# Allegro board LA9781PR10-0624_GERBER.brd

Outline 305.85 x 179.2 mm; copper layers: TOP, GND1, IN1, VCC, IN2, IN3, GND2, IN4, GND3, BOTTOM. Coordinates in mm from the lower left corner of the outline.

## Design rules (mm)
net group BUS_CSS: nets CSSN_1 CSSP_1
net group BUS_FDI-CTL: nets FDI_CSYNC FDI_INT
net group BUS_SMB: nets GPU_SMBCLK_R GPU_SMBDAT_R
net group BUS_SVID: nets PECI_EC PECI_EC_R
net group CLK_CPU_DMI: nets CLK_CPU_DMI CPU_DMI
net group CLK_CPU_DMI#: nets CLK_CPU_DMI# CPU_DMI#
net group CLK_CPU_DPLL: nets CLK_CPU_DPLL CPU_DPLL
net group CLK_CPU_DPLL#: nets CLK_CPU_DPLL# CPU_DPLL#
net group CLK_CPU_SSC_DPLL: nets CLK_CPU_SSC_DPLL CPU_SSC_DPLL
net group CLK_CPU_SSC_DPLL#: nets CLK_CPU_SSC_DPLL# CPU_SSC_DPLL#
net group CLK_PCIE_CARD: nets CLK_PCIE_CARD PCIE_CARD
net group CLK_PCIE_CARD#: nets CLK_PCIE_CARD# PCIE_CARD#
net group CLK_PCIE_EXP: nets CLK_PCIE_EXP PCIE_EXP
net group CLK_PCIE_EXP#: nets CLK_PCIE_EXP# PCIE_EXP#
net group CLK_PCIE_LAN: nets CLK_PCIE_LAN PCIE_LAN
net group CLK_PCIE_LAN#: nets CLK_PCIE_LAN# PCIE_LAN#
net group CLK_PCIE_MINI1: nets CLK_PCIE_MINI1 PCIE_MINI1
net group CLK_PCIE_MINI1#: nets CLK_PCIE_MINI1# PCIE_MINI1#
net group CLK_PCIE_MINI3: nets CLK_PCIE_MINI3 PCIE_MINI3
net group CLK_PCIE_MINI3#: nets CLK_PCIE_MINI3# PCIE_MINI3#
net group CLK_PCIE_NVR: nets CLK_PCIE_NVR PCIE_NVR
net group CLK_PCIE_NVR#: nets CLK_PCIE_NVR# PCIE_NVR#
net group DDR_XDP_WAN_SMBCLK: nets DDR_XDP_WAN_SMBCLK DDR_XDP_WAN_SMBCLK_R2
net group DDR_XDP_WAN_SMBDAT: nets DDR_XDP_WAN_SMBDAT DDR_XDP_WAN_SMBDAT_R2
net group DIFFPAIR0: nets MXM_CURI2C_CLK MXM_CURI2C_DATA
net group DP_CARD_SMBCD: nets CARD_SMBCLK CARD_SMBDAT
net group DP_CHARGER_SMBCD: nets CHARGER_SMBCLK CHARGER_SMBDAT
net group DP_CLK_BUF_BCLK: nets CLK_BUF_BCLK CLK_BUF_BCLK#
net group DP_CLK_BUF_DMI: nets CLK_BUF_DMI CLK_BUF_DMI#
net group DP_CLK_PCIE_MINI2: nets CLK_PCIE_MINI2 CLK_PCIE_MINI2#
net group DP_DOCK_SMBCD: nets DOCK_SMB_CLK DOCK_SMB_DAT
net group DP_DPC_DOCK_SW_AUX: nets DPC_DOCK_SW_AUX DPC_DOCK_SW_AUX#
net group DP_DPD_DOCK_AUX: nets DPD_DOCK_AUX DPD_DOCK_AUX#
net group DP_EDP_CPU_AUX-R: nets EDP_CPU_AUX#_R EDP_CPU_AUX_R
net group DP_GPU_SMBCD: nets GPU_SMBCLK GPU_SMBDAT
net group DP_LAN_SMBCD: nets LAN_SMBCLK LAN_SMBDATA
net group DP_LAN_TX0: nets LAN_TX0+R LAN_TX0-R
net group DP_LAN_TX1+R: nets LAN_TX1+R LAN_TX1-R
net group DP_LAN_TX2: nets LAN_TX2+ LAN_TX2-
net group DP_LAN_TX2+R: nets LAN_TX2+R LAN_TX2-R
net group DP_LAN_TX3: nets LAN_TX3+ LAN_TX3-
net group DP_LCD_SMBCD: nets LCD_SMBCLK LCD_SMBDAT
net group DP_LDDC-SW: nets LDDC_CLK_SW LDDC_DATA_SW
net group DP_LVDS_B0: nets LVDS_B0+ LVDS_B0-
net group DP_MEM_SMBCD: nets MEM_SMBCLK MEM_SMBDATA
net group DP_MUX_AUX: nets MUX_AUX MUX_AUX#
net group DP_PBAT_SMBCD: nets PBAT_SMBCLK PBAT_SMBDAT
net group DP_SML1_SMBCD: nets SML1_SMBCLK SML1_SMBDATA
net group DP_SW_LVDS_A0: nets SW_LVDS_A0+ SW_LVDS_A0-
net group DP_SW_LVDS_A1: nets SW_LVDS_A1+ SW_LVDS_A1-
net group DP_SW_LVDS_A2: nets SW_LVDS_A2+ SW_LVDS_A2-
net group DP_SW_LVDS_ACLK: nets SW_LVDS_ACLK+ SW_LVDS_ACLK-
net group DP_SW_LVDS_B0: nets SW_LVDS_B0+ SW_LVDS_B0-
net group DP_SW_LVDS_B1: nets SW_LVDS_B1+ SW_LVDS_B1-
net group DP_SW_LVDS_B2: nets SW_LVDS_B2+ SW_LVDS_B2-
net group DP_SW_LVDS_BCLK: nets SW_LVDS_BCLK+ SW_LVDS_BCLK-
net group DP_USB3R5: nets USB3RN5 USB3RP5
net group DP_USB3R6: nets USB3RN6 USB3RP6
net group DP_USB3T3: nets USB3TN3 USB3TP3
net group DP_USB3T5: nets USB3TN5 USB3TP5
net group DP_USB3T6: nets USB3TN6 USB3TP6
net group DP_USBP1: nets USBP1+ USBP1-
net group DP_USBP2: nets USBP2+ USBP2-
net group DP_USBP5: nets USBP5+ USBP5-
net group DP_USBP9: nets USBP9+ USBP9-
net group DP_USBP10: nets USBP10+ USBP10-
net group DP_USBP11: nets USBP11+ USBP11-
net group DP_USH_SMBCD: nets USH_SMBCLK USH_SMBDAT
net group DP_Z430_SMBCD: nets Z4304 Z4305
net group DPD_CPU_LANE_N0: nets DPD_CPU_LANE_N0 DPD_CPU_LANE_N0_C
net group DPD_CPU_LANE_N1: nets DPD_CPU_LANE_N1 DPD_CPU_LANE_N1_C
net group DPD_CPU_LANE_N2: nets DPD_CPU_LANE_N2 DPD_CPU_LANE_N2_C
net group DPD_CPU_LANE_N3: nets DPD_CPU_LANE_N3 DPD_CPU_LANE_N3_C
net group DPD_CPU_LANE_P0: nets DPD_CPU_LANE_P0 DPD_CPU_LANE_P0_C
net group DPD_CPU_LANE_P1: nets DPD_CPU_LANE_P1 DPD_CPU_LANE_P1_C
net group DPD_CPU_LANE_P2: nets DPD_CPU_LANE_P2 DPD_CPU_LANE_P2_C
net group DPD_CPU_LANE_P3: nets DPD_CPU_LANE_P3 DPD_CPU_LANE_P3_C
net group MB_DP_RP_C_N0: nets MB_DP_RP_C_N0 MB_DP_RP_N0
net group MB_DP_RP_C_N1: nets MB_DP_RP_C_N1 MB_DP_RP_N1
net group MB_DP_RP_C_N2: nets MB_DP_RP_C_N2 MB_DP_RP_N2
net group MB_DP_RP_C_N3: nets MB_DP_RP_C_N3 MB_DP_RP_N3
net group MB_DP_RP_C_P0: nets MB_DP_RP_C_P0 MB_DP_RP_P0
net group MB_DP_RP_C_P1: nets MB_DP_RP_C_P1 MB_DP_RP_P1
net group MB_DP_RP_C_P2: nets MB_DP_RP_C_P2 MB_DP_RP_P2
net group MB_DP_RP_C_P3: nets MB_DP_RP_C_P3 MB_DP_RP_P3
net group MSATA_PRX_DTX_N4: nets MSATA_PRX_DTX_N4 MSATA_PRX_DTX_N4_C
net group MSATA_PRX_DTX_P4: nets MSATA_PRX_DTX_P4 MSATA_PRX_DTX_P4_C
net group MSATA_PTX_DRX_N4: nets MSATA_PTX_DRX_N4 MSATA_PTX_DRX_N4_C
net group MSATA_PTX_DRX_P4: nets MSATA_PTX_DRX_P4 MSATA_PTX_DRX_P4_C
net group MUX_D0: nets MUX_D0 MUX_D0_C
net group MUX_D0#: nets MUX_D0# MUX_D0#_C
net group MUX_D1: nets MUX_D1 MUX_D1_C
net group MUX_D1#: nets MUX_D1# MUX_D1#_C
net group MUX_D2: nets MUX_D2 MUX_D2_C
net group MUX_D2#: nets MUX_D2# MUX_D2#_C
net group MUX_D3: nets MUX_D3 MUX_D3_C
net group MUX_D3#: nets MUX_D3# MUX_D3#_C
net group MXM_DPC_AUX: nets MXM_DPC_AUX MXM_DPC_AUX_C
net group MXM_DPC_AUX#: nets MXM_DPC_AUX# MXM_DPC_AUX#_C
net group MXM_DPC_N0: nets MXM_DPC_N0 MXM_DPC_N0_C
net group MXM_DPC_N1: nets MXM_DPC_N1 MXM_DPC_N1_C
net group MXM_DPC_N2: nets MXM_DPC_N2 MXM_DPC_N2_C
net group MXM_DPC_N3: nets MXM_DPC_N3 MXM_DPC_N3_C
net group MXM_DPC_P0: nets MXM_DPC_P0 MXM_DPC_P0_C
net group MXM_DPC_P1: nets MXM_DPC_P1 MXM_DPC_P1_C
net group MXM_DPC_P2: nets MXM_DPC_P2 MXM_DPC_P2_C
net group MXM_DPC_P3: nets MXM_DPC_P3 MXM_DPC_P3_C
net group MXM_EDP_AUX+: nets MXM_EDP_AUX+ MXM_EDP_AUX+_C
net group MXM_EDP_AUX-: nets MXM_EDP_AUX- MXM_EDP_AUX-_C
net group MXM_EDP_TX0+: nets MXM_EDP_TX0+ MXM_EDP_TX0+_C
net group MXM_EDP_TX0-: nets MXM_EDP_TX0- MXM_EDP_TX0-_C
net group MXM_EDP_TX1+: nets MXM_EDP_TX1+ MXM_EDP_TX1+_C
net group MXM_EDP_TX1-: nets MXM_EDP_TX1- MXM_EDP_TX1-_C
net group MXM_EDP_TX2+: nets MXM_EDP_TX2+ MXM_EDP_TX2+_C
net group MXM_EDP_TX2-: nets MXM_EDP_TX2- MXM_EDP_TX2-_C
net group MXM_EDP_TX3+: nets MXM_EDP_TX3+ MXM_EDP_TX3+_C
net group MXM_EDP_TX3-: nets MXM_EDP_TX3- MXM_EDP_TX3-_C
net group MXM_MB_DP_N0: nets MXM_MB_DP_N0 MXM_MB_DP_N0_C
net group MXM_MB_DP_N1: nets MXM_MB_DP_N1 MXM_MB_DP_N1_C
net group MXM_MB_DP_N2: nets MXM_MB_DP_N2 MXM_MB_DP_N2_C
net group MXM_MB_DP_N3: nets MXM_MB_DP_N3 MXM_MB_DP_N3_C
net group MXM_MB_DP_P0: nets MXM_MB_DP_P0 MXM_MB_DP_P0_C
net group MXM_MB_DP_P1: nets MXM_MB_DP_P1 MXM_MB_DP_P1_C
net group MXM_MB_DP_P2: nets MXM_MB_DP_P2 MXM_MB_DP_P2_C
net group MXM_MB_DP_P3: nets MXM_MB_DP_P3 MXM_MB_DP_P3_C
net group NB_LAN_TX0+: nets NB_LAN_TX0+ NB_LAN_TX0+_R
net group NB_LAN_TX0-: nets NB_LAN_TX0- NB_LAN_TX0-_R
net group NB_LAN_TX1+: nets NB_LAN_TX1+ NB_LAN_TX1+_R
net group NB_LAN_TX1-: nets NB_LAN_TX1- NB_LAN_TX1-_R
net group PCH_DDPD_AUX: nets PCH_DDPD_AUX PCH_DDPD_AUX_C
net group PCH_DDPD_AUX#: nets PCH_DDPD_AUX# PCH_DDPD_AUX#_C
net group PCIE_PRX_GLANTX_N2: nets PCIE_PRX_GLANTX_N2 PCIE_PRX_GLANTX_N2_C
net group PCIE_PRX_GLANTX_P2: nets PCIE_PRX_GLANTX_P2 PCIE_PRX_GLANTX_P2_C
net group PCIE_PTX_GLANRX_N2: nets PCIE_PTX_GLANRX_N2 PCIE_PTX_GLANRX_N2_C
net group PCIE_PTX_GLANRX_P2: nets PCIE_PTX_GLANRX_P2 PCIE_PTX_GLANRX_P2_C
net group PCIE_PTX_WANRX_N5: nets PCIE_PTX_WANRX_N5 PCIE_PTX_WANRX_N5_C
net group PCIE_PTX_WANRX_P5: nets PCIE_PTX_WANRX_P5 PCIE_PTX_WANRX_P5_C
net group PCIE_PTX_WLANRX_N3: nets PCIE_PTX_WLANRX_N3 PCIE_PTX_WLANRX_N3_C
net group PCIE_PTX_WLANRX_P3: nets PCIE_PTX_WLANRX_P3 PCIE_PTX_WLANRX_P3_C
net group PCIE_PTX_WPANRX_N6: nets PCIE_PTX_WPANRX_N6 PCIE_PTX_WPANRX_N6_C
net group PCIE_PTX_WPANRX_P6: nets PCIE_PTX_WPANRX_P6 PCIE_PTX_WPANRX_P6_C
net group PEG_CRX_GTX_C_N0: nets PEG_CRX_GTX_C_N0 PEG_CRX_GTX_N0
net group PEG_CRX_GTX_C_N1: nets PEG_CRX_GTX_C_N1 PEG_CRX_GTX_N1
net group PEG_CRX_GTX_C_N2: nets PEG_CRX_GTX_C_N2 PEG_CRX_GTX_N2
net group PEG_CRX_GTX_C_N3: nets PEG_CRX_GTX_C_N3 PEG_CRX_GTX_N3
net group PEG_CRX_GTX_C_N4: nets PEG_CRX_GTX_C_N4 PEG_CRX_GTX_N4
net group PEG_CRX_GTX_C_N5: nets PEG_CRX_GTX_C_N5 PEG_CRX_GTX_N5
net group PEG_CRX_GTX_C_N6: nets PEG_CRX_GTX_C_N6 PEG_CRX_GTX_N6
net group PEG_CRX_GTX_C_N7: nets PEG_CRX_GTX_C_N7 PEG_CRX_GTX_N7
net group PEG_CRX_GTX_C_N8: nets PEG_CRX_GTX_C_N8 PEG_CRX_GTX_N8
net group PEG_CRX_GTX_C_N9: nets PEG_CRX_GTX_C_N9 PEG_CRX_GTX_N9
net group PEG_CRX_GTX_C_N10: nets PEG_CRX_GTX_C_N10 PEG_CRX_GTX_N10
net group PEG_CRX_GTX_C_N11: nets PEG_CRX_GTX_C_N11 PEG_CRX_GTX_N11
net group PEG_CRX_GTX_C_N12: nets PEG_CRX_GTX_C_N12 PEG_CRX_GTX_N12
net group PEG_CRX_GTX_C_N13: nets PEG_CRX_GTX_C_N13 PEG_CRX_GTX_N13
net group PEG_CRX_GTX_C_N14: nets PEG_CRX_GTX_C_N14 PEG_CRX_GTX_N14
net group PEG_CRX_GTX_C_N15: nets PEG_CRX_GTX_C_N15 PEG_CRX_GTX_N15
net group PEG_CRX_GTX_C_P0: nets PEG_CRX_GTX_C_P0 PEG_CRX_GTX_P0
net group PEG_CRX_GTX_C_P1: nets PEG_CRX_GTX_C_P1 PEG_CRX_GTX_P1
net group PEG_CRX_GTX_C_P2: nets PEG_CRX_GTX_C_P2 PEG_CRX_GTX_P2
net group PEG_CRX_GTX_C_P3: nets PEG_CRX_GTX_C_P3 PEG_CRX_GTX_P3
net group PEG_CRX_GTX_C_P4: nets PEG_CRX_GTX_C_P4 PEG_CRX_GTX_P4
net group PEG_CRX_GTX_C_P5: nets PEG_CRX_GTX_C_P5 PEG_CRX_GTX_P5
net group PEG_CRX_GTX_C_P6: nets PEG_CRX_GTX_C_P6 PEG_CRX_GTX_P6
net group PEG_CRX_GTX_C_P7: nets PEG_CRX_GTX_C_P7 PEG_CRX_GTX_P7
net group PEG_CRX_GTX_C_P8: nets PEG_CRX_GTX_C_P8 PEG_CRX_GTX_P8
net group PEG_CRX_GTX_C_P9: nets PEG_CRX_GTX_C_P9 PEG_CRX_GTX_P9
net group PEG_CRX_GTX_C_P10: nets PEG_CRX_GTX_C_P10 PEG_CRX_GTX_P10
net group PEG_CRX_GTX_C_P11: nets PEG_CRX_GTX_C_P11 PEG_CRX_GTX_P11
net group PEG_CRX_GTX_C_P12: nets PEG_CRX_GTX_C_P12 PEG_CRX_GTX_P12
net group PEG_CRX_GTX_C_P13: nets PEG_CRX_GTX_C_P13 PEG_CRX_GTX_P13
net group PEG_CRX_GTX_C_P14: nets PEG_CRX_GTX_C_P14 PEG_CRX_GTX_P14
net group PEG_CRX_GTX_C_P15: nets PEG_CRX_GTX_C_P15 PEG_CRX_GTX_P15
net group PEG_CTX_GRX_C_N0: nets PEG_CTX_GRX_C_N0 PEG_CTX_GRX_N0
net group PEG_CTX_GRX_C_N1: nets PEG_CTX_GRX_C_N1 PEG_CTX_GRX_N1
net group PEG_CTX_GRX_C_N2: nets PEG_CTX_GRX_C_N2 PEG_CTX_GRX_N2
net group PEG_CTX_GRX_C_N3: nets PEG_CTX_GRX_C_N3 PEG_CTX_GRX_N3
net group PEG_CTX_GRX_C_N4: nets PEG_CTX_GRX_C_N4 PEG_CTX_GRX_N4
net group PEG_CTX_GRX_C_N5: nets PEG_CTX_GRX_C_N5 PEG_CTX_GRX_N5
net group PEG_CTX_GRX_C_N6: nets PEG_CTX_GRX_C_N6 PEG_CTX_GRX_N6
net group PEG_CTX_GRX_C_N7: nets PEG_CTX_GRX_C_N7 PEG_CTX_GRX_N7
net group PEG_CTX_GRX_C_N8: nets PEG_CTX_GRX_C_N8 PEG_CTX_GRX_N8
net group PEG_CTX_GRX_C_N9: nets PEG_CTX_GRX_C_N9 PEG_CTX_GRX_N9
net group PEG_CTX_GRX_C_N10: nets PEG_CTX_GRX_C_N10 PEG_CTX_GRX_N10
net group PEG_CTX_GRX_C_N11: nets PEG_CTX_GRX_C_N11 PEG_CTX_GRX_N11
net group PEG_CTX_GRX_C_N12: nets PEG_CTX_GRX_C_N12 PEG_CTX_GRX_N12
net group PEG_CTX_GRX_C_N13: nets PEG_CTX_GRX_C_N13 PEG_CTX_GRX_N13
net group PEG_CTX_GRX_C_N14: nets PEG_CTX_GRX_C_N14 PEG_CTX_GRX_N14
net group PEG_CTX_GRX_C_N15: nets PEG_CTX_GRX_C_N15 PEG_CTX_GRX_N15
net group PEG_CTX_GRX_C_P0: nets PEG_CTX_GRX_C_P0 PEG_CTX_GRX_P0
net group PEG_CTX_GRX_C_P1: nets PEG_CTX_GRX_C_P1 PEG_CTX_GRX_P1
net group PEG_CTX_GRX_C_P2: nets PEG_CTX_GRX_C_P2 PEG_CTX_GRX_P2
net group PEG_CTX_GRX_C_P3: nets PEG_CTX_GRX_C_P3 PEG_CTX_GRX_P3
net group PEG_CTX_GRX_C_P4: nets PEG_CTX_GRX_C_P4 PEG_CTX_GRX_P4
net group PEG_CTX_GRX_C_P5: nets PEG_CTX_GRX_C_P5 PEG_CTX_GRX_P5
net group PEG_CTX_GRX_C_P6: nets PEG_CTX_GRX_C_P6 PEG_CTX_GRX_P6
net group PEG_CTX_GRX_C_P7: nets PEG_CTX_GRX_C_P7 PEG_CTX_GRX_P7
net group PEG_CTX_GRX_C_P8: nets PEG_CTX_GRX_C_P8 PEG_CTX_GRX_P8
net group PEG_CTX_GRX_C_P9: nets PEG_CTX_GRX_C_P9 PEG_CTX_GRX_P9
net group PEG_CTX_GRX_C_P10: nets PEG_CTX_GRX_C_P10 PEG_CTX_GRX_P10
net group PEG_CTX_GRX_C_P11: nets PEG_CTX_GRX_C_P11 PEG_CTX_GRX_P11
net group PEG_CTX_GRX_C_P12: nets PEG_CTX_GRX_C_P12 PEG_CTX_GRX_P12
net group PEG_CTX_GRX_C_P13: nets PEG_CTX_GRX_C_P13 PEG_CTX_GRX_P13
net group PEG_CTX_GRX_C_P14: nets PEG_CTX_GRX_C_P14 PEG_CTX_GRX_P14
net group PEG_CTX_GRX_C_P15: nets PEG_CTX_GRX_C_P15 PEG_CTX_GRX_P15
net group SATA_ODD_PRX_DTX_N1: nets SATA_ODD_PRX_DTX_N1 SATA_ODD_PRX_DTX_N1_C
net group SATA_ODD_PRX_DTX_P1: nets SATA_ODD_PRX_DTX_P1 SATA_ODD_PRX_DTX_P1_C
net group SATA_ODD_PTX_DRX_N1: nets SATA_ODD_PTX_DRX_N1 SATA_ODD_PTX_DRX_N1_C
net group SATA_ODD_PTX_DRX_P1: nets SATA_ODD_PTX_DRX_P1 SATA_ODD_PTX_DRX_P1_C
net group SATA_PRX_DKTX_N2: nets SATA_PRX_DKTX_N2 SATA_PRX_DKTX_N2_C
net group SATA_PRX_DKTX_P2: nets SATA_PRX_DKTX_P2 SATA_PRX_DKTX_P2_C
net group SATA_PRX_DTX_N5: nets SATA_PRX_DTX_N5 SATA_PRX_DTX_N5_C
net group SATA_PRX_DTX_P5: nets SATA_PRX_DTX_P5 SATA_PRX_DTX_P5_C
net group SATA_PTX_DKRX_N2: nets SATA_PTX_DKRX_N2 SATA_PTX_DKRX_N2_C
net group SATA_PTX_DKRX_P2: nets SATA_PTX_DKRX_P2 SATA_PTX_DKRX_P2_C
net group SATA_PTX_DRX_N5: nets SATA_PTX_DRX_N5 SATA_PTX_DRX_N5_C
net group SATA_PTX_DRX_P5: nets SATA_PTX_DRX_P5 SATA_PTX_DRX_P5_C
net group SCLK: nets SCLK VIDSCLK
net group SDA: nets SDA VIDSOUT
net group TMDSE_CON_CLK: nets TMDSE_CON_CLK TMDSE_RP_CLK
net group TMDSE_CON_CLK#: nets TMDSE_CON_CLK# TMDSE_RP_CLK#
net group TMDSE_CON_N0: nets TMDSE_CON_N0 TMDSE_RP_N0
net group TMDSE_CON_N1: nets TMDSE_CON_N1 TMDSE_RP_N1
net group TMDSE_CON_N2: nets TMDSE_CON_N2 TMDSE_RP_N2
net group TMDSE_CON_P0: nets TMDSE_CON_P0 TMDSE_RP_P0
net group TMDSE_CON_P1: nets TMDSE_CON_P1 TMDSE_RP_P1
net group TMDSE_CON_P2: nets TMDSE_CON_P2 TMDSE_RP_P2
net group USB3RN1: nets USB3RN1 USB3RN1_C
net group USB3RN1_RP: nets USB3RN1_RP USB3RN1_RP_R
net group USB3RN2: nets USB3_RX2_N_D- USB3RN2
net group USB3RP1: nets USB3RP1 USB3RP1_C
net group USB3RP1_RP: nets USB3RP1_RP USB3RP1_RP_R
net group USB3RP2: nets USB3_RX2_P_D+ USB3RP2
net group USB3TN1: nets USB3TN1 USB3TN1_C
net group USB3TN1_RP: nets USB3TN1_RP USB3TN1_RP_C
net group USB3TP1: nets USB3TP1 USB3TP1_C
net group USB3TP1_RP: nets USB3TP1_RP USB3TP1_RP_C
net group USBP0+: nets USBP0+ USBP0_D+
net group USBP0-: nets USBP0- USBP0_D-
net group USBP1_D+: nets USBP1_D+ USBP1_R_D+
net group USBP1_D-: nets USBP1_D- USBP1_R_D-
net group USBP8+: nets USBP8+ USBP8_D+
net group USBP8-: nets USBP8- USBP8_D-
net group USBP12+: nets USBP12+ USBP12_D+
net group USBP12-: nets USBP12- USBP12_D-
net group USBP13+: nets USBP13+ USBP13_D+
net group USBP13-: nets USBP13- USBP13_D-
net group 10: nets +DC_IN_SS REM_DIODE1_N_4021 REM_DIODE1_P_4021
net group ALERT#: nets ALERT# H_CPU_SVIDALRT# VIDALERT_N
net group BUS_AC97: nets PCH_AZ_BITCLK PCH_AZ_CODEC_BITCLK PCH_AZ_CODEC_RST# PCH_AZ_CODEC_SDIN0 PCH_AZ_CODEC_SDOUT PCH_AZ_CODEC_SYNC PCH_AZ_RST# PCH_AZ_SDOUT PCH_AZ_SYNC SPKR
net group BUS_CLK: nets PCH_SPI_CLK SPI_CLK32 SPI_CLK64 SPI_PCH_CLK SUSCLK
net group BUS_CLK-FLEX: nets CLK_PCI_TPM
net group BUS_COMP: nets DMI_RCOMP EDP_COMP PEG_COMP SATA_COMP SM_RCOMP0 SM_RCOMP1 SM_RCOMP2
net group BUS_CPU: nets DDR3_DRAMRST#_CPU DDR3_DRAMRST#_R DDR_HVREF_RST_PCH H_CATERR# H_CPUPWRGD H_CPUPWRGD_XDP H_PM_SYNC H_PROCHOT# H_PROCHOT#_R H_THERMTRIP# H_THERMTRIP#_R PCH_JTAG_TCK PCH_JTAG_TMS PCH_PLTRST# PCH_PLTRST#_BUF PCH_PLTRST#_EC PLTRST_GPU# PLTRST_LAN# PLTRST_MMI# PLTRST_USH# PM_DRAM_PWRGD PM_DRAM_PWRGD_R PROCHOT#_EC RUNPWROK THERMATRIP2# XDP_RST#_R XDP_TCLK
net group BUS_CRT-DAC: nets BLUE_CRT BLUE_CRT_L BLUE_DOCK GREEN_CRT GREEN_CRT_L GREEN_DOCK MXM_CRT_BLU MXM_CRT_GRN MXM_CRT_RED PCH_CRT_BLU PCH_CRT_GRN PCH_CRT_RED RED_CRT RED_CRT_L RED_DOCK
net group BUS_CRT-DDC: nets CLK_DDC2_CRT CLK_DDC2_DOCK DAT_DDC2_CRT DAT_DDC2_DOCK MXM_CRT_DDC_CLK MXM_CRT_DDC_DAT PCH_CRT_DDC_CLK PCH_CRT_DDC_DAT
net group BUS_CRT-SYNC: nets HSYNC_BUF HSYNC_DOCK HSYNC_L MXM_CRT_HSYNC MXM_CRT_VSYNC PCH_CRT_HSYNC PCH_CRT_VSYNC VSYNC_BUF VSYNC_DOCK VSYNC_L
net group BUS_CTL-LINK: nets PCH_CL_CLK1 PCH_CL_DATA1 PCH_CL_RST1#
net group BUS_DDRA-CMD: nets DDR_A_BS0 DDR_A_BS1 DDR_A_BS2 DDR_A_CAS# DDR_A_MA0 DDR_A_MA1 DDR_A_MA2 DDR_A_MA3 DDR_A_MA4 DDR_A_MA5 DDR_A_MA6 DDR_A_MA7 DDR_A_MA8 DDR_A_MA9 DDR_A_MA10 DDR_A_MA11 DDR_A_MA12 DDR_A_MA13 DDR_A_MA14 DDR_A_MA15 DDR_A_RAS# DDR_A_WE#
net group BUS_DDRA-CTL: nets DDR_CKE0_DIMM2 DDR_CKE1_DIMM2 DDR_CKE4_DIMM1 DDR_CKE5_DIMM1 DDR_CS0_DIMM2# DDR_CS1_DIMM2# DDR_CS4_DIMM1# DDR_CS5_DIMM1# M_ODT0 M_ODT1 M_ODT4 M_ODT5
net group BUS_DDRA-D0: nets DDR_A_D0 DDR_A_D1 DDR_A_D2 DDR_A_D3 DDR_A_D4 DDR_A_D5 DDR_A_D6 DDR_A_D7
net group BUS_DDRA-D1: nets DDR_A_D8 DDR_A_D9 DDR_A_D10 DDR_A_D11 DDR_A_D12 DDR_A_D13 DDR_A_D14 DDR_A_D15
net group BUS_DDRA-D2: nets DDR_A_D16 DDR_A_D17 DDR_A_D18 DDR_A_D19 DDR_A_D20 DDR_A_D21 DDR_A_D22 DDR_A_D23
net group BUS_DDRA-D3: nets DDR_A_D24 DDR_A_D25 DDR_A_D26 DDR_A_D27 DDR_A_D28 DDR_A_D29 DDR_A_D30 DDR_A_D31
net group BUS_DDRA-D4: nets DDR_A_D32 DDR_A_D33 DDR_A_D34 DDR_A_D35 DDR_A_D36 DDR_A_D37 DDR_A_D38 DDR_A_D39
net group BUS_DDRA-D5: nets DDR_A_D40 DDR_A_D41 DDR_A_D42 DDR_A_D43 DDR_A_D44 DDR_A_D45 DDR_A_D46 DDR_A_D47
net group BUS_DDRA-D6: nets DDR_A_D48 DDR_A_D49 DDR_A_D50 DDR_A_D51 DDR_A_D52 DDR_A_D53 DDR_A_D54 DDR_A_D55
net group BUS_DDRA-D7: nets DDR_A_D56 DDR_A_D57 DDR_A_D58 DDR_A_D59 DDR_A_D60 DDR_A_D61 DDR_A_D62 DDR_A_D63
net group BUS_DDRB-CMD: nets DDR_B_BS0 DDR_B_BS1 DDR_B_BS2 DDR_B_CAS# DDR_B_MA0 DDR_B_MA1 DDR_B_MA2 DDR_B_MA3 DDR_B_MA4 DDR_B_MA5 DDR_B_MA6 DDR_B_MA7 DDR_B_MA8 DDR_B_MA9 DDR_B_MA10 DDR_B_MA11 DDR_B_MA12 DDR_B_MA13 DDR_B_MA14 DDR_B_MA15 DDR_B_RAS# DDR_B_WE#
net group BUS_DDRB-CTL: nets DDR_CKE2_DIMM4 DDR_CKE3_DIMM4 DDR_CKE6_DIMM3 DDR_CKE7_DIMM3 DDR_CS2_DIMM4# DDR_CS3_DIMM4# DDR_CS6_DIMM3# DDR_CS7_DIMM3# M_ODT2 M_ODT3 M_ODT6 M_ODT7
net group BUS_DDRB-D0: nets DDR_B_D0 DDR_B_D1 DDR_B_D2 DDR_B_D3 DDR_B_D4 DDR_B_D5 DDR_B_D6 DDR_B_D7
net group BUS_DDRB-D1: nets DDR_B_D8 DDR_B_D9 DDR_B_D10 DDR_B_D11 DDR_B_D12 DDR_B_D13 DDR_B_D14 DDR_B_D15
net group BUS_DDRB-D2: nets DDR_B_D16 DDR_B_D17 DDR_B_D18 DDR_B_D19 DDR_B_D20 DDR_B_D21 DDR_B_D22 DDR_B_D23
net group BUS_DDRB-D3: nets DDR_B_D24 DDR_B_D25 DDR_B_D26 DDR_B_D27 DDR_B_D28 DDR_B_D29 DDR_B_D30 DDR_B_D31
net group BUS_DDRB-D4: nets DDR_B_D32 DDR_B_D33 DDR_B_D34 DDR_B_D35 DDR_B_D36 DDR_B_D37 DDR_B_D38 DDR_B_D39
net group BUS_DDRB-D5: nets DDR_B_D40 DDR_B_D41 DDR_B_D42 DDR_B_D43 DDR_B_D44 DDR_B_D45 DDR_B_D46 DDR_B_D47
net group BUS_DDRB-D6: nets DDR_B_D48 DDR_B_D49 DDR_B_D50 DDR_B_D51 DDR_B_D52 DDR_B_D53 DDR_B_D54 DDR_B_D55
net group BUS_DDRB-D7: nets DDR_B_D56 DDR_B_D57 DDR_B_D58 DDR_B_D59 DDR_B_D60 DDR_B_D61 DDR_B_D62 DDR_B_D63
net group BUS_HDMI: nets HDMI_SCL_SINK HDMI_SDA_SINK PCH_DDPD_CTRLCLK PCH_DDPD_CTRLDATA
net group BUS_LAN: nets LAN_TX0+ LAN_TX0- LAN_TX1+ LAN_TX1- LAN_TX3+R LAN_TX3-R
net group BUS_LVDS-CTL: nets LCD_EDID_CLK LCD_EDID_DATA MXM_LVDS_DDC_CLK MXM_LVDS_DDC_DAT
net group BUS_PCIE: nets PCIE_PRX_EXPTX_N7 PCIE_PRX_EXPTX_P7 PCIE_PRX_MMITX_N8 PCIE_PRX_MMITX_P8 PCIE_PRX_WANTX_N5 PCIE_PRX_WANTX_P5 PCIE_PRX_WLANTX_N3 PCIE_PRX_WLANTX_P3 PCIE_PRX_WPANTX_N6 PCIE_PRX_WPANTX_P6 PCIE_PTX_EXPRX_N7 PCIE_PTX_EXPRX_P7 PCIE_PTX_MMIRX_N8 PCIE_PTX_MMIRX_P8
net group BUS_REM-DIDOE: nets REM_DIODE1_N REM_DIODE1_P REM_DIODE2_N REM_DIODE2_P REM_DIODE3_N REM_DIODE3_P REM_DIODE4_N REM_DIODE4_P
net group BUS_RTC: nets PCH_RTCRST# PCH_RTCX1 PCH_RTCX1_R PCH_RTCX2 SRTCRST#
net group BUS_SENSE: nets VCCSENSE VCCSENSE_R VSSSENSE VSSSENSE_R
net group BUS_SPI: nets SPI_DIN32 SPI_DIN64 SPI_DO32 SPI_DO64 SPI_PCH_CS0# SPI_PCH_CS0#_R SPI_PCH_CS1# SPI_PCH_CS1#_R SPI_PCH_DIN SPI_PCH_DO SPI_WP#_SEL
net group BUS_UIM: nets UIM_CLK UIM_DATA UIM_RESET
net group BUS_XDP: nets XDP_DBRESET# XDP_DBRESET#_R XDP_FN0 XDP_FN1 XDP_FN2 XDP_FN3 XDP_FN4 XDP_FN5 XDP_FN6 XDP_FN7 XDP_FN8 XDP_FN9 XDP_FN10 XDP_FN11 XDP_FN12 XDP_FN13 XDP_FN14 XDP_FN15 XDP_FN16 XDP_FN17 XDP_OBS0_R XDP_OBS1_R XDP_OBS2_R XDP_OBS3_R XDP_OBS4_R XDP_OBS5_R XDP_OBS6_R XDP_OBS7_R XDP_PRDY# XDP_PREQ# XDP_TDI XDP_TDI_R XDP_TDO XDP_TDO_R XDP_TMS XDP_TRST#
net group CLK_BCLK_ITP: nets CLK_BCLK_ITP CLK_CPU_ITP CLK_XDP
net group CLK_BCLK_ITP#: nets CLK_BCLK_ITP# CLK_CPU_ITP# CLK_XDP#
net group DPC_DOCK_AUX: nets DPC_DOCK_AUX
net group DPC_DOCK_AUX#: nets DPC_DOCK_AUX#
net group DPC_DOCK_LANE_C_N0: nets DPC_DOCK_LANE_C_N0 DPC_DOCK_LANE_N0_R MXM_DPB_N0
net group DPC_DOCK_LANE_C_N1: nets DPC_DOCK_LANE_C_N1 DPC_DOCK_LANE_N1_R MXM_DPB_N1
net group DPC_DOCK_LANE_C_N2: nets DPC_DOCK_LANE_C_N2 DPC_DOCK_LANE_N2_R MXM_DPB_N2
net group DPC_DOCK_LANE_C_N3: nets DPC_DOCK_LANE_C_N3 DPC_DOCK_LANE_N3_R MXM_DPB_N3
net group DPC_DOCK_LANE_C_P0: nets DPC_DOCK_LANE_C_P0 DPC_DOCK_LANE_P0_R MXM_DPB_P0
net group DPC_DOCK_LANE_C_P1: nets DPC_DOCK_LANE_C_P1 DPC_DOCK_LANE_P1_R MXM_DPB_P1
net group DPC_DOCK_LANE_C_P2: nets DPC_DOCK_LANE_C_P2 DPC_DOCK_LANE_P2_R MXM_DPB_P2
net group DPC_DOCK_LANE_C_P3: nets DPC_DOCK_LANE_C_P3 DPC_DOCK_LANE_P3_R MXM_DPB_P3
net group DPD_DOCK_LANE_N0: nets DPD_DOCK_LANE_N0 DPD_DOCK_LANE_N0_R DPD_GPU_LANE_N0
net group DPD_DOCK_LANE_N1: nets DPD_DOCK_LANE_N1 DPD_DOCK_LANE_N1_R DPD_GPU_LANE_N1
net group DPD_DOCK_LANE_N2: nets DPD_DOCK_LANE_N2 DPD_DOCK_LANE_N2_R DPD_GPU_LANE_N2
net group DPD_DOCK_LANE_N3: nets DPD_DOCK_LANE_N3 DPD_DOCK_LANE_N3_R DPD_GPU_LANE_N3
net group DPD_DOCK_LANE_P0: nets DPD_DOCK_LANE_P0 DPD_DOCK_LANE_P0_R DPD_GPU_LANE_P0
net group DPD_DOCK_LANE_P1: nets DPD_DOCK_LANE_P1 DPD_DOCK_LANE_P1_R DPD_GPU_LANE_P1
net group DPD_DOCK_LANE_P2: nets DPD_DOCK_LANE_P2 DPD_DOCK_LANE_P2_R DPD_GPU_LANE_P2
net group DPD_DOCK_LANE_P3: nets DPD_DOCK_LANE_P3 DPD_DOCK_LANE_P3_R DPD_GPU_LANE_P3
net group ESATA_PRX_DTX_N3: nets ESATA_PRX_DTX_N3 ESATA_PRX_DTX_N3_BP ESATA_PRX_DTX_N3_C ESATA_PRX_DTX_N3_RP SATA_PRX_DTX_N3
net group ESATA_PRX_DTX_P3: nets ESATA_PRX_DTX_P3 ESATA_PRX_DTX_P3_BP ESATA_PRX_DTX_P3_C ESATA_PRX_DTX_P3_RP SATA_PRX_DTX_P3
net group ESATA_PTX_DRX_N3: nets ESATA_PTX_DRX_N3 ESATA_PTX_DRX_N3_BP ESATA_PTX_DRX_N3_C ESATA_PTX_DRX_N3_RP SATA_PTX_DRX_N3
net group ESATA_PTX_DRX_P3: nets ESATA_PTX_DRX_P3 ESATA_PTX_DRX_P3_BP ESATA_PTX_DRX_P3_C ESATA_PTX_DRX_P3_RP SATA_PTX_DRX_P3
net group MXM_MB_DP_AUX: nets MXM_MB_DP_AUX_C
net group MXM_MB_DP_AUX#: nets MXM_MB_DP_AUX#_C
net group PSATA_PRX_DTX_N0: nets PSATA_PRX_DTX_N0 PSATA_PRX_DTX_N0_BP PSATA_PRX_DTX_N0_C PSATA_PRX_DTX_N0_RP SATA_PRX_DTX_N0
net group PSATA_PRX_DTX_P0: nets PSATA_PRX_DTX_P0 PSATA_PRX_DTX_P0_BP PSATA_PRX_DTX_P0_C PSATA_PRX_DTX_P0_RP SATA_PRX_DTX_P0
net group PSATA_PTX_DRX_N0: nets PSATA_PTX_DRX_N0 PSATA_PTX_DRX_N0_BP PSATA_PTX_DRX_N0_C PSATA_PTX_DRX_N0_RP SATA_PTX_DRX_N0
net group PSATA_PTX_DRX_P0: nets PSATA_PTX_DRX_P0 PSATA_PTX_DRX_P0_BP PSATA_PTX_DRX_P0_C PSATA_PTX_DRX_P0_RP SATA_PTX_DRX_P0
net group USB3TN2: nets USB3_TX2_N_D- USB3TN2 USB3TN2_C
net group USB3TP2: nets USB3_TX2_P_D+ USB3TP2 USB3TP2_C
nets with their own width: min track width 0.102; nets 1.5V_RUN_PWRGD 1.5VSP_FB +CRT_VCC +DC_IN REM_DIODE2_N_4021 REM_DIODE2_P_4021 Z4306
nets with their own width: min track width 0.203; nets MEC_XTAL1 MEC_XTAL2 MEC_XTAL2_R XTALI XTALO XTALO_R
nets with their own width: min track width 0.254; nets 1.05V_A_PWRGD 3301_ACAV_IN_NB +VCHGR ACAV_DOCK_SRC# ACAV_IN ACAVIN BLK_MOSFET_GC CD3301_SDC_IN CD_PBATT_OFF CPU_VTT_ON CSSN_2 CSSP_2 DC_BLOCK_GC DK_AC_OFF DK_AC_OFF_EN DK_CSS_GC DSCHRG_MOSFET_GC EN_1.5VSP N17319754 P1_SW P2_SW P3_SW PWM3 REGCTL_PNP10 SL_BAT_PRES# STSTART_DCBLOCK_GC
nets with their own width: min track width 0.305; nets FFS_INT2 FFS_INT2_Q HDD_FALL_INT
nets with their own width: min track width 0.381; nets N17708032 N17708061 SOFT_START_GC
nets with their own width: min track width 0.508; nets +1.05V_M +1.05V_RUN +1.5V_RUN +1.35V_MEM +3.3V_ALW +3.3V_ALW2 +3.3V_ALW_PCH +3.3V_ALW_U46 +3.3V_M +3.3V_RTC_LDO +3.3V_RUN +3.3V_RUN_PS8513 +3.3V_SPI +3.3V_SUS +3.3V_VTR +5V_ALW +5V_ALW_ESATA +5V_RUN +AVCC33 +DIMM4_VREF_CA +DIMM4_VREF_DQ +DOCK_PWR_BAR +DVCC33 +LOM_VCT +MXM_PWR +MXM_PWR_R +MXM_PWR_SRC +MXM_PWR_SRC_R +NBDOCK_DC_IN_SS +PCH_VCCDSW3_3 +PECI_VREF +PWR_SRC +PWR_SRC_MXM +PWR_SRC_S +RTC_CELL +SDC_IN +TRM_CT1 +TRM_CT2 +TRM_CT3 +TRM_CT4 +V_DDR_REF +VCC_CORE +VCCIO2PCH +VCCIO2PCH_R +VCCIO_OUT +VCCST +VR_CAP BLKNG_MOSFET_GC BST_5V ERC1 GND N85751870 PBATT+ SNUB_1.5VSP
nets with their own width: min track width 0.635; nets BOOT1 BOOT2 BOOT3 BST1_5V BST_3V PHASE3 SNUB_3V SNUB_5V UGATE3
nets with their own width: min track width 0.762; nets 1.5VSP_VIN UG_5V
nets with their own width: min track width 1.016; nets +3.3V_LAN +3.3V_PCIE_NVM +3.3V_RUN_TPM +DP_VCC +VDISPLAY_VCC LG_3V PHASE2 UGATE1
nets with their own width: min track width 1.524; nets +SW_LX +SWR_V12
nets with their own width: min track width 2.032; nets +3.3V_PCIE_FLASH +3.3V_WLAN +5V_ALW_FUSE +5V_HDD +5V_USB_PWR2 +EDPVDD
nets with their own width: min track width 2.54; nets +5V_ESATA_PWR
nets with their own width: min track width 4.064; nets +5V_MOD

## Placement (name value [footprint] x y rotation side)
C1  -  [C_0603]  34.2 132.02 0 top
C2  -  [C_0805]  34.14 130.49 0 top
C3  -  [C_0603]  34.2 133.29 0 top
C4  -  [C_0402]  34.52 134.43 0 top
C5  -  [C_0805]  202.46 58.5 270 bottom
C7  -  [C_0402]  43.46 134.3 0 top
C8  -  [C_0402]  115.92 144.34 0 top
C12  -  [C_0402]  86.26 163.26 0 bottom
C13  -  [C_0402]  88.95 163.26 180 bottom
C14  -  [C_0402]  89.38 167.88 90 bottom
C15  -  [C_0402]  90.79 167.67 270 top
C18  -  [C_0402]  88.54 167.58 0 top
C19  -  [C_0402]  87.3 167.58 180 top
C20  -  [C_0402]  81.38 160.85 0 bottom
C21  -  [C_0402]  78.84 161.99 0 bottom
C22  -  [C_0402]  89.76 161.1 0 bottom
C23  -  [C_0402]  85.44 161.1 180 bottom
C24  -  [C_0402]  183.36 42.18 270 bottom
C25  -  [C_0402]  10.08 147.36 180 top
C45  -  [C_0402]  258.22 61.41 0 bottom
C46  -  [C_0402]  38.38 164.35 270 bottom
C47  -  [C_0805]  39.38 163.89 0 bottom
C48  -  [C_0402]  258.21 62.68 0 bottom
C51  -  [C_0402]  112.83 30.93 180 top
C54  -  [C_0402]  119.78 30.29 0 top
C55  -  [C_0402]  112.88 32.83 180 top
C56  -  [C_0402]  113.31 29.27 180 top
C86  -  [C_0402]  35.46 149.04 0 top
C87  -  [C_0402]  279.32 69.53 180 bottom
C88  -  [C_0402]  291.11 69.66 0 bottom
C90  -  [C_0402]  109.32 130.42 90 top
C92  -  [C_0402]  112.5 130.42 90 top
C94  -  [C_0402]  122.4 136.64 90 top
C95  -  [C_0402]  117.07 136.64 90 top
C96  -  [C_0402]  119.73 136.64 90 top
C97  -  [C_0402]  30.5 122.87 0 bottom
C100  -  [C_0402]  129.18 145.1 0 bottom
C101  -  [C_0402]  129.18 144.21 0 bottom
C103  -  [C_0402]  129.18 143.19 0 bottom
C104  -  [C_0402]  129.18 146.11 0 bottom
C105  -  [C_0402]  129.18 147 0 bottom
C106  -  [C_0603]  127.93 147 180 top
C107  -  [C_0402]  127.3 145.86 180 top
C108  -  [C_0402]  127.3 144.97 180 top
C109  -  [C_0603]  128.18 138.88 0 bottom
C110  -  [C_0402]  128.17 140.02 0 bottom
C111  -  [C_0402]  127.18 143.19 180 top
C112  -  [C_0402]  123.49 151.32 180 bottom
C113  -  [C_0603]  119.23 140.21 270 bottom
C114  -  [C_0402]  120.37 139.97 270 bottom
C115  -  [C_0603]  122.4 140.21 270 bottom
C116  -  [C_0402]  123.54 139.97 270 bottom
C117  -  [C_0402]  121.26 139.97 270 bottom
C118  -  [C_0402]  129.18 142.3 0 bottom
C243  -  [C_0402]  89.03 152.59 0 top
C244  -  [C_0402]  118.85 168.26 90 top
C248  -  [C_0402]  104.44 168.97 180 bottom
C249  -  [C_0603]  95.71 155.84 90 bottom
C250  -  [C_0603]  128.46 156.9 270 bottom
C270  -  [C_0402]  37.82 97.73 180 bottom
C272  -  [C_0402]  203.05 73.88 270 bottom
C273  -  [C_0402]  55.92 99.68 90 top
C274  -  [C_0402]  30.28 96.33 180 bottom
C277  -  [C_0402]  36.68 88.53 270 bottom
C279  -  [C_0402]  282.55 67.55 90 bottom
C280  -  [C_0402]  286.36 67.55 90 bottom
C281  -  [C_0402]  284.45 67.55 90 bottom
C282  -  [C_0402]  281.53 67.55 90 bottom
C283  -  [C_0402]  285.34 67.55 90 bottom
C284  -  [C_0402]  289.15 67.55 90 bottom
C285  -  [C_0402]  290.17 67.55 90 bottom
C286  -  [C_0402]  283.44 67.55 90 bottom
C287  -  [C_0402]  41.68 100.9 0 bottom
C288  -  [C_0402]  204.95 153.43 270 bottom
C289  -  [C_0402]  57.2 56.96 180 bottom
C290  -  [C_0402]  57.2 58.23 180 bottom
C291  -  [C_0402]  40.61 93.59 90 bottom
C292  -  [C_0402]  251.36 41.85 0 bottom
C294  -  [C_0402]  39.6 94.5 270 bottom
C295  -  [C_0402]  286.23 81.04 270 bottom
C296  -  [C_0603]  96.9 157.24 270 bottom
C297  -  [C_1206]  101.85 155.47 90 bottom
C298  -  [C_0402]  92.09 157.26 180 bottom
C299  -  [C_0402]  2.67 131.01 0 top
C300  -  [C_0805]  2.27 129.72 0 top
C301  -  [C_0402]  29.39 111.27 0 top
C302  -  [C_0402]  281.53 81.04 270 bottom
C303  -  [C_0402]  282.42 81.04 270 bottom
C304  -  [C_0402]  287.25 81.04 270 bottom
C305  -  [C_0402]  123.54 151.65 270 top
C306  -  [C_0402]  284.33 81.04 270 bottom
C307  -  [C_0402]  288.14 81.04 270 bottom
C308  -  [C_0402]  285.34 81.04 270 bottom
C309  -  [C_0402]  283.44 81.04 270 bottom
C310  -  [C_0402]  7.97 115.89 315 top
C311  -  [C_0402]  5.69 118.17 135 top
C313  -  [C_0402]  289.61 140.27 180 top
C319  -  [C_0402]  39.52 92.52 0 bottom
C320  -  [C_0402]  236.45 54.09 90 bottom
C323  -  [C_APXK2R5ARA331MF451]  286.5 89.49 0 bottom
C324  -  [C_APXK2R5ARA331MF451]  287.53 101.81 90 bottom
C327  -  [C_0402]  247.67 54.04 0 bottom
C328  -  [C_0603]  41.31 134.3 180 top
C329  -  [C_0805]  227.72 87.99 90 top
C330  -  [C_0805]  13.22 88.84 0 bottom
C332  -  [C_0603]  115.67 145.48 0 top
C339  -  [C_0402]  189.16 120.83 90 top
C340  -  [C_0402]  186.92 44.95 90 top
C343  -  [C_0402]  230.83 42.32 180 bottom
C356  -  [C_0805]  42.81 129.48 0 top
C359  -  [C_0402]  54.96 112.76 90 bottom
C362  -  [C_0603]  108.75 174.56 180 top
C364  -  [C_0402]  226.39 88.19 90 top
C366  -  [C_0402]  82.78 112.15 270 bottom
C367  -  [C_0402]  83.67 112.15 270 bottom
C368  -  [C_0402]  84.68 112.15 270 bottom
C369  -  [C_0402]  85.57 112.15 270 bottom
C370  -  [C_0402]  13.23 87.44 0 bottom
C371  -  [C_0402]  110.36 150.71 90 top
C372  -  [C_0402]  118.87 150.71 90 top
C373  -  [C_0402]  109.47 150.71 90 top
C374  -  [C_0402]  117.98 150.71 90 top
C375  -  [C_0402]  116.97 150.71 90 top
C376  -  [C_0402]  116.08 150.71 90 top
C377  -  [C_0402]  115.06 150.71 90 top
C378  -  [C_0402]  114.17 150.71 90 top
C379  -  [C_0402]  113.16 150.71 90 top
C380  -  [C_0402]  112.27 150.71 90 top
C383  -  [C_0402]  188.77 35.88 180 bottom
C384  -  [C_0402]  188.77 36.77 180 bottom
C385  -  [C_0402]  188.77 37.78 180 bottom
C386  -  [C_0402]  188.77 38.67 180 bottom
C387  -  [C_0402]  56.49 110.48 90 bottom
C388  -  [C_0402]  57.5 110.48 90 bottom
C389  -  [C_0402]  188.77 36.77 180 top
C390  -  [C_0402]  188.77 35.88 180 top
C391  -  [C_0402]  175.74 39 270 top
C392  -  [C_0603]  173.39 42.61 180 top
C393  -  [C_0402]  188.77 38.67 180 top
C394  -  [C_0402]  188.77 37.78 180 top
C395  -  [C_0402]  203.73 60.01 0 bottom
C396  -  [C_0603]  115.16 168.4 90 top
C397  -  [C_0402]  291.31 73.14 90 bottom
C398  -  [C_0402]  292.2 73.14 90 bottom
C400  -  [C_0603]  109.7 167.89 270 top
C402  -  [C_0402]  32.23 148.98 270 top
C403  -  [C_0402]  203.73 51.12 0 bottom
C404  -  [C_0402]  203.73 50.1 0 bottom
C405  -  [C_0402]  25.25 159.88 90 top
C406  -  [C_0402]  203.73 58.99 0 bottom
C407  -  [C_0402]  78.28 36.13 180 top
C408  -  [C_0402]  78.28 35.24 180 top
C409  -  [C_0402]  86.33 35.17 90 top
C410  -  [C_0402]  22.91 152.21 180 top
C411  -  [C_0402]  66.39 34.91 90 top
C412  -  [C_0402]  70.2 34.91 90 top
C413  -  [C_0402]  65.51 34.91 90 top
C414  -  [C_0402]  69.32 34.91 90 top
C415  -  [C_0402]  85.32 35.17 90 top
C416  -  [C_0603]  69.82 38.48 90 top
C417  -  [C_0402]  71.73 35.42 90 top
C418  -  [C_0402]  179.88 37.78 180 bottom
C419  -  [C_0402]  186.28 41.26 90 bottom
C420  -  [C_0402]  181.96 33.41 270 bottom
C421  -  [C_0402]  179.88 38.67 180 bottom
C422  -  [C_0402]  179.88 36.77 180 bottom
C423  -  [C_0402]  179.88 35.88 180 bottom
C424  -  [C_0402]  86.59 112.15 270 bottom
C425  -  [C_0402]  87.48 112.15 270 bottom
C426  -  [C_0402]  88.49 112.15 270 bottom
C427  -  [C_0402]  89.38 112.15 270 bottom
C428  -  [C_0402]  27.58 25.59 0 top
C429  -  [C_0402]  27.58 24.7 0 top
C430  -  [C_0402]  27.46 35.5 0 top
C431  -  [C_0402]  82.9 132.96 90 bottom
C432  -  [C_0402]  27.46 36.39 0 top
C433  -  [C_0402]  27.46 40.2 0 top
C434  -  [C_0402]  27.46 39.31 0 top
C435  -  [C_0402]  72.62 35.42 90 top
C436  -  [C_0402]  42.82 128.08 0 top
C437  -  [C_0402]  33.5 160.01 90 top
C438  -  [C_0402]  83.79 132.96 90 bottom
C439  -  [C_0402]  84.81 132.96 90 bottom
C440  -  [C_0402]  85.7 132.96 90 bottom
C441  -  [C_0402]  86.71 132.96 90 bottom
C442  -  [C_0402]  87.6 132.96 90 bottom
C443  -  [C_0402]  88.62 132.96 90 bottom
C444  -  [C_0402]  89.51 132.96 90 bottom
C445  -  [C_0402]  24.87 160.8 270 bottom
C446  -  [C_0402]  25.75 160.8 270 bottom
C447  -  [C_0402]  21.69 160.8 270 bottom
C448  -  [C_0402]  22.58 160.8 270 bottom
C449  -  [C_0603]  74.52 37.97 90 top
C450  -  [C_0402]  268.07 79.39 270 bottom
C452  -  [C_0402]  266.88 73.47 180 bottom
C453  -  [C_0402]  274.72 71.57 0 bottom
C454  -  [C_0402]  266.88 72.58 180 bottom
C456  -  [C_0402]  281.7 97.98 180 top
C457  -  [C_0402]  281.7 97.09 180 top
C458  -  [C_0402]  109.7 86.63 270 top
C459  -  [C_0402]  110.59 86.63 270 top
C460  -  [C_0402]  111.61 85.71 90 top
C461  -  [C_0402]  112.5 85.71 90 top
C462  -  [C_0603]  110.72 86.87 270 bottom
C463  -  [C_0402]  113.99 88.86 90 bottom
C464  -  [C_0603]  114.65 90.74 90 bottom
C465  -  [C_0402]  265.96 74.49 0 bottom
C466  -  [C_0402]  116.99 91.5 0 top
C467  -  [C_0402]  110.34 95.01 270 bottom
C468  -  [C_0402]  112.75 95.01 270 bottom
C469  -  [C_0402]  113.1 88.86 90 bottom
C470  -  [C_0402]  118.08 93.61 270 top
C471  -  [C_0402]  118.08 94.48 90 top
C472  -  [C_0402]  105.13 100.98 270 top
C473  -  [C_0402]  117.07 103.62 90 top
C474  -  [C_0402]  105.13 103.62 90 top
C475  -  [C_0603]  105.05 37.72 270 top
C476  -  [C_0402]  105.66 38.67 180 top
C477  -  [C_0402]  105.66 39.69 180 top
C478  -  [C_0402]  103.48 94.35 90 top
C479  -  [C_0603]  55.35 145.67 270 bottom
C480  -  [C_0603]  54.08 145.67 270 bottom
C481  -  [C_0603]  44.87 162.12 180 top
C482  -  [C_0805]  290 138.98 180 top
C483  -  [C_0402]  44.63 163.26 180 top
C484  -  [C_0603]  47.73 145.67 270 bottom
C485  -  [C_1808]  64.63 156.02 180 bottom
C486  -  [C_0603]  46.46 145.67 270 bottom
C487  -  [C_0402]  265.96 75.38 0 bottom
C488  -  [C_0402]  275.64 73.6 180 bottom
C489  -  [C_0402]  275.64 72.71 180 bottom
C494  -  [C_0402]  31.16 118.56 180 bottom
C495  -  [C_0402]  31.42 123.89 180 bottom
C496  -  [C_0402]  279.32 76.65 180 bottom
C497  -  [C_0402]  280.64 68.47 270 bottom
C498  -  [C_0805]  87.73 35.28 90 top
C499  -  [C_0402]  39.42 112.33 180 bottom
C504  -  [C_0402]  38.2 126.61 90 bottom
C505  -  [C_0402]  36.37 151.7 180 top
C506  -  [C_0402]  36.37 152.59 180 top
C507  -  [C_0402]  36.37 153.48 180 top
C508  -  [C_0402]  36.37 154.37 180 top
C509  -  [C_0402]  36.37 155.26 180 top
C510  -  [C_0402]  36.37 156.15 180 top
C511  -  [C_0402]  36.37 157.04 180 top
C512  -  [C_0402]  36.37 157.93 180 top
C513  -  [C_0603]  104.88 40.64 90 top
C514  -  [C_0805]  58.81 18.35 0 bottom
C515  -  [C_0402]  42.09 118.3 180 bottom
C516  -  [C_0402]  42.09 119.19 180 bottom
C517  -  [C_0402]  42.09 116.4 180 bottom
C518  -  [C_0402]  42.09 117.29 180 bottom
C519  -  [C_0402]  42.09 114.49 180 bottom
C520  -  [C_0402]  42.09 115.38 180 bottom
C521  -  [C_0402]  42.09 113.48 180 bottom
C522  -  [C_0402]  42.09 112.59 180 bottom
C523  -  [C_0402]  42.09 126.81 180 bottom
C524  -  [C_0402]  42.09 124.91 180 bottom
C525  -  [C_0402]  42.09 125.92 180 bottom
C526  -  [C_0402]  42.09 123 180 bottom
C527  -  [C_0402]  42.09 124.02 180 bottom
C528  -  [C_0402]  42.09 120.21 180 bottom
C529  -  [C_0402]  42.09 122.11 180 bottom
C530  -  [C_0402]  42.09 121.1 180 bottom
C531  -  [C_0402]  35.15 112.51 90 bottom
C532  -  [C_0402]  34.26 112.51 90 bottom
C533  -  [C_0402]  32.36 112.51 90 bottom
C534  -  [C_0402]  33.25 112.51 90 bottom
C536  -  [C_0603]  102.72 170.18 90 top
C538  -  [C_0402]  103.86 171.34 270 top
C539  -  [C_0402]  108.63 169.48 180 top
C540  -  [C_0603]  94.3 167.15 180 top
C541  -  [C_0402]  272.59 41.85 180 bottom
C542  -  [C_0402]  13.05 146.16 90 bottom
C543  -  [C_0402]  59.87 16.96 180 bottom
C544  -  [C_0402]  27.46 34.48 0 top
C545  -  [C_0402]  59.87 15.94 180 bottom
C546  -  [C_0603]  58.71 14.8 0 bottom
C547  -  [C_0402]  102.34 77.46 90 top
C550  -  [C_0402]  248.33 62.68 180 bottom
C551  -  [C_0402]  258.22 58.48 0 bottom
C552  -  [C_0402]  258.21 59.37 0 bottom
C553  -  [C_0402]  248.33 61.79 180 bottom
C595  -  [C_0402]  116.94 157.37 270 bottom
C596  -  [C_0402]  125.83 170.96 270 bottom
C597  -  [C_0402]  272.97 49.85 180 bottom
C598  -  [C_0402]  126.72 170.96 270 bottom
C599  -  [C_0402]  272.97 48.96 180 bottom
C601  -  [C_0402]  110.72 170.83 270 bottom
C603  -  [C_0402]  124.05 157.24 270 bottom
C604  -  [C_0402]  133.91 157.29 180 bottom
C605  -  [C_0402]  113.51 157.24 270 bottom
C606  -  [C_0402]  123.16 156.32 90 bottom
C607  -  [C_0402]  129.89 170.96 270 bottom
C608  -  [C_0603]  111.1 157.48 270 bottom
C610  -  [C_0402]  259.13 41 180 bottom
C611  -  [C_0402]  272.01 46.64 90 bottom
C612  -  [C_0402]  259.13 52.52 180 bottom
C613  -  [C_0805]  273.4 46.12 90 bottom
C614  -  [C_0402]  259.13 64.62 180 bottom
C615  -  [C_APXK2R5ARA331MF451]  284.21 50.17 270 bottom
C616  -  [C_0402]  263.12 20.69 90 bottom
C617  -  [C_0402]  28.04 159.88 90 bottom
C618  -  [C_0402]  28.93 159.88 90 bottom
C619  -  [C_V]  14.2 149.54 90 top
C621  -  [C_0402]  22.07 147.08 270 bottom
C622  -  [C_0805]  4.61 142.75 270 bottom
C623  -  [C_0402]  33.25 147.21 270 bottom
C624  -  [C_0402]  72.11 17.92 270 bottom
C626  -  [C_0402]  74.52 17.01 90 bottom
C628  -  [C_0402]  266.55 20.69 90 bottom
C629  -  [C_0402]  264.26 20.69 90 bottom
C630  -  [C_0402]  265.4 20.69 90 bottom
C631  -  [C_0402]  268.07 20.69 90 bottom
C633  -  [C_0603]  65.76 30.73 90 bottom
C634  -  [C_0402]  66.9 30.72 90 bottom
C636  -  [C_0402]  75.41 17.01 90 bottom
C637  -  [C_0402]  78.08 31.64 270 bottom
C638  -  [C_0402]  90.02 31.64 270 bottom
C639  -  [C_0402]  71.22 17.92 270 bottom
C643  -  [C_0402]  262.23 20.69 90 bottom
C645  -  [C_0603]  261.09 20.7 90 bottom
C661  -  [C_0402]  2.16 150.66 90 top
C662  -  [C_0402]  2.13 148.4 90 top
C663  -  [C_0402]  4.04 145.81 270 top
C664  -  [C_0402]  4.93 145.81 270 top
C665  -  [C_0402]  6.32 145.81 270 top
C666  -  [C_0402]  7.21 145.81 270 top
C667  -  [C_D2]  20.52 165.16 0 bottom
C668  -  [C_0402]  19.84 166.69 0 top
C669  -  [C_0805]  293.09 58.74 180 bottom
C670  -  [C_0402]  297.41 60.01 0 bottom
C671  -  [C_0402]  3.02 153.28 90 top
C672  -  [C_0402]  3.91 153.28 90 top
C673  -  [C_0402]  4.93 153.28 90 top
C674  -  [C_0402]  5.82 153.28 90 top
C675  -  [C_0402]  18.26 160.47 180 top
C676  -  [C_0805]  19.15 159.07 180 top
C677  -  [C_0402]  5.82 153.23 90 bottom
C678  -  [C_0402]  3.91 153.23 90 bottom
C679  -  [C_0402]  3.02 153.23 90 bottom
C680  -  [C_0402]  4.93 153.23 90 bottom
C695  -  [C_0402]  91.29 114.31 270 bottom
C696  -  [C_0402]  91.16 131.05 90 bottom
C697  -  [C_0402]  95.35 131.97 270 bottom
C698  -  [C_0402]  96.24 131.97 270 bottom
C699  -  [C_0402]  97.26 131.05 90 bottom
C700  -  [C_0402]  98.14 131.05 90 bottom
C701  -  [C_0402]  112.75 131.05 90 bottom
C702  -  [C_0603]  124.05 113.54 270 bottom
C703  -  [C_0603]  80.36 114.17 270 bottom
C704  -  [C_0402]  112.88 113.4 90 bottom
C708  -  [C_0402]  243.18 61.48 270 bottom
C709  -  [C_0402]  247.06 71.18 180 bottom
C710  -  [C_0402]  230.3 70.17 180 bottom
C712  -  [C_0402]  232.89 60.57 90 bottom
C713  -  [C_0402]  237.59 60.57 90 bottom
C714  -  [C_0603]  230.29 69.03 180 bottom
C715  -  [C_0402]  280.66 83.35 0 bottom
C716  -  [C_0402]  234.16 77.33 90 bottom
C717  -  [C_0402]  235.76 61.41 180 bottom
C718  -  [C_0402]  230.3 71.06 180 bottom
C719  -  [C_0402]  236.96 77.33 90 bottom
C720  -  [C_0402]  235.3 57.93 270 bottom
C721  -  [C_0402]  11.4 67.96 270 top
C722  -  [C_0402]  21.44 65.16 270 top
C723  -  [C_0402]  21.44 102.68 270 top
C724  -  [C_0402]  22.58 80.58 0 top
C725  -  [C_0402]  21.74 78.3 0 top
C726  -  [C_0402]  105.76 164.73 270 bottom
C727  -  [C_0402]  97 164.07 90 bottom
C733  -  [C_0402]  233.4 38.47 90 bottom
C734  -  [C_0402]  235.51 39.38 270 bottom
C735  -  [C_0402]  246.61 38.24 270 bottom
C736  -  [C_0402]  243.94 38.24 270 bottom
C737  -  [C_0402]  240.89 54.09 90 bottom
C739  -  [C_0402]  239.11 54.09 90 bottom
C740  -  [C_0402]  250.98 40.07 0 bottom
C741  -  [C_0402]  238.3 36.64 180 bottom
C742  -  [C_0402]  235.38 46.55 180 bottom
C743  -  [C_0402]  239.29 36.64 0 bottom
C744  -  [C_0402]  232.18 46.55 0 bottom
C746  -  [C_0402]  101.65 69.28 180 bottom
C747  -  [C_0402]  244.83 55.99 90 bottom
C748  -  [C_0402]  292.96 109.08 90 bottom
C753  -  [C_0402]  293.98 109.08 90 bottom
C754  -  [C_0402]  296.01 109.08 90 bottom
C756  -  [C_0402]  128.5 98.57 270 top
C757  -  [C_0402]  243.05 38.24 270 bottom
C758  -  [C_0402]  127.48 98.57 270 top
C759  -  [C_0402]  278.28 94.04 0 top
C762  -  [C_0603]  275.25 40.32 0 bottom
C763  -  [C_0402]  11.31 64.49 90 top
C764  -  [C_0603]  15.21 144.91 270 bottom
C766  -  [C_0603]  33.37 148.97 270 top
C767  -  [C_0603]  27.6 26.73 0 top
C770  -  [C_0603]  101.19 77.42 90 top
C772  -  [C_0603]  45.82 75.18 90 top
C773  -  [C_0402]  43.79 75.17 90 top
C774  -  [C_0402]  14.27 133.16 180 top
C776  -  [C_1206]  27.66 130.94 270 top
C777  -  [C_0402]  250.85 52.9 0 bottom
C778  -  [C_0402]  33.37 88.41 270 top
C779  -  [C_0603]  233.08 47.69 180 bottom
C780  -  [C_0402]  248.64 38.24 270 bottom
C781  -  [C_0402]  250.98 45.91 0 bottom
C782  -  [C_0603]  250.8 53.85 90 bottom
C783  -  [C_0603]  39.34 126.62 90 bottom
C793  -  [C_0603]  291.44 113.55 270 bottom
C794  -  [C_0603]  290.85 90.56 180 bottom
C1145  -  [C_0402]  90.65 147.43 90 top
C1146  -  [C_0402]  89.76 147.43 90 top
C1149  -  [C_0402]  76.94 151.88 90 bottom
C1159  -  [C_0402]  77.82 151.88 90 bottom
C1167  -  [C_0402]  65.68 160.47 0 top
C1174  -  [C_0402]  69.44 113.4 90 bottom
C1176  -  [C_D2E]  276.2 43.5 0 bottom
C1177  -  [C_0805]  109.19 87.19 270 bottom
C1178  -  [C_0805]  115.92 88.33 270 bottom
C1179  -  [C_0402]  37.57 88.53 270 bottom
C1181  -  [C_0402]  91.57 102.68 180 bottom
C1182  -  [C_0603]  93.64 109.79 180 bottom
C1183  -  [C_0402]  84.94 155.51 90 bottom
C1184  -  [C_0402]  86.21 155.51 90 bottom
C1185  -  [C_0402]  79.48 155.39 90 bottom
C1186  -  [C_0402]  78.21 155.39 90 bottom
C1188  -  [C_0402]  88.75 158.37 90 bottom
C1216  -  [C_0402]  101.65 62.04 180 bottom
C1332  -  [C_0402]  23.42 149.29 180 top
C1333  -  [C_0402]  35.74 165.8 180 top
C1334  -  [C_0402]  36.6 165.8 0 top
C1335  -  [C_0402]  33.04 165.8 0 top
C1336  -  [C_0402]  32.18 165.8 180 top
C1337  -  [C_0402]  29.49 165.8 0 top
C1338  -  [C_0402]  28.62 165.8 180 top
C1339  -  [C_0402]  25.93 165.8 0 top
C1340  -  [C_0402]  25.07 165.8 180 top
C1341  -  [C_0402]  289.15 60.08 270 bottom
C1343  -  [C_0402]  234.47 49.09 0 bottom
C1345  -  [C_0402]  235.38 41.42 180 bottom
C1346  -  [C_0402]  234.54 52.44 90 bottom
C1348  -  [C_0402]  235.38 47.44 180 bottom
C1349  -  [C_0402]  240 54.09 90 bottom
C1350  -  [C_0402]  235.38 50.23 180 bottom
C1351  -  [C_0402]  234.47 51.5 0 bottom
C1352  -  [C_0402]  235.18 36.18 90 bottom
C1353  -  [C_0402]  241.27 38.24 270 bottom
C1354  -  [C_0402]  235.18 34.91 270 bottom
C1355  -  [C_0402]  244.75 54.09 90 bottom
CC1  -  [C_0402]  77.44 139.05 90 bottom
CC2  -  [C_0402]  76.05 136.51 90 bottom
CC3  -  [C_0402]  74.52 139.05 90 bottom
CC4  -  [C_0402]  70.97 136.51 90 bottom
CC5  -  [C_0402]  69.57 139.18 90 bottom
CC6  -  [C_0402]  68.05 136.51 90 bottom
CC7  -  [C_0402]  66.52 139.18 90 bottom
CC8  -  [C_0402]  65 136.51 90 bottom
CC9  -  [C_0402]  63.47 140.09 270 bottom
CC10  -  [C_0402]  61.95 137.43 270 bottom
CC11  -  [C_0402]  61.31 140.09 270 bottom
CC12  -  [C_0402]  59.03 137.43 270 bottom
CC13  -  [C_0402]  57.5 139.18 90 bottom
CC14  -  [C_0402]  55.98 136.51 90 bottom
CC15  -  [C_0402]  54.33 139.18 90 bottom
CC16  -  [C_0402]  66.04 132.93 0 bottom
CC17  -  [C_0402]  78.33 139.05 90 bottom
CC18  -  [C_0402]  76.94 136.51 90 bottom
CC19  -  [C_0402]  75.41 139.05 90 bottom
CC20  -  [C_0402]  71.86 136.51 90 bottom
CC21  -  [C_0402]  70.46 139.18 90 bottom
CC22  -  [C_0402]  68.93 136.51 90 bottom
CC23  -  [C_0402]  67.41 139.18 90 bottom
CC24  -  [C_0402]  65.89 136.51 90 bottom
CC25  -  [C_0402]  64.36 140.09 270 bottom
CC26  -  [C_0402]  62.84 137.43 270 bottom
CC27  -  [C_0402]  60.43 140.09 270 bottom
CC28  -  [C_0402]  59.92 137.43 270 bottom
CC29  -  [C_0402]  58.39 139.18 90 bottom
CC30  -  [C_0402]  56.87 136.51 90 bottom
CC31  -  [C_0402]  55.22 139.18 90 bottom
CC32  -  [C_0402]  66.04 133.82 0 bottom
CC33  -  [C_0805]  169.09 117.13 90 top
CC34  -  [C_0805]  171.12 117.13 90 top
CC35  -  [C_0805]  173.16 117.13 90 top
CC36  -  [C_0805]  175.19 117.13 90 top
CC37  -  [C_0805]  177.22 117.13 90 top
CC38  -  [C_0805]  179 117.13 90 top
CC39  -  [C_0805]  180.78 117.13 90 top
CC40  -  [C_0805]  182.55 117.13 90 top
CC41  -  [C_0805]  184.33 117.13 90 top
CC42  -  [C_0805]  186.11 117.13 90 top
CC43  -  [C_0805]  187.89 117.13 90 top
CC44  -  [C_0402]  77.82 147.82 90 top
CC45  -  [C_0402]  76.05 147.82 90 top
CC46  -  [C_0402]  70.71 147.82 90 top
CC47  -  [C_0402]  67.16 147.82 90 top
CC48  -  [C_0402]  61.82 147.82 90 top
CC49  -  [C_0402]  56.49 147.82 90 top
CC50  -  [C_0402]  51.15 147.82 90 top
CC51  -  [C_0402]  75.16 147.82 90 top
CC52  -  [C_0402]  73.38 147.82 90 top
CC53  -  [C_0402]  74.27 147.82 90 top
CC54  -  [C_0402]  69.82 147.82 90 top
CC55  -  [C_0402]  68.05 147.82 90 top
CC56  -  [C_0402]  65.38 147.82 90 top
CC57  -  [C_0402]  64.49 147.82 90 top
CC58  -  [C_0402]  62.71 147.82 90 top
CC59  -  [C_0402]  60.04 147.82 90 top
CC60  -  [C_0402]  59.16 147.82 90 top
CC61  -  [C_0402]  57.38 147.82 90 top
CC62  -  [C_0402]  54.71 147.82 90 top
CC63  -  [C_0402]  53.82 147.82 90 top
CC64  -  [C_0402]  52.04 147.82 90 top
CC65  -  [C_0402]  206.17 123.51 180 top
CC66  -  [C_0402]  206.17 124.4 180 top
CC67  -  [C_0402]  78.71 147.82 90 top
CC68  -  [C_0402]  76.94 147.82 90 top
CC69  -  [C_0402]  71.6 147.82 90 top
CC70  -  [C_0402]  66.27 147.82 90 top
CC71  -  [C_0402]  60.93 147.82 90 top
CC72  -  [C_0402]  55.6 147.82 90 top
CC73  -  [C_0402]  72.49 147.82 90 top
CC74  -  [C_0402]  68.93 147.82 90 top
CC75  -  [C_0402]  63.6 147.82 90 top
CC76  -  [C_0402]  58.27 147.82 90 top
CC77  -  [C_0402]  52.93 147.82 90 top
CC78  -  [C_0805]  201.94 141.16 0 top
CC79  -  [C_0805]  201.94 139.38 0 top
CC137  -  [C_0603]  155.99 128.08 0 top
CC138  -  [C_0402]  205.33 112.56 0 top
CC140  -  [C_0402]  209.27 147.71 270 top
CC156  -  [C_0402]  202.49 105.09 180 top
CC161  -  [C_0805]  169.09 117.13 90 bottom
CC162  -  [C_0805]  175.19 117.13 90 bottom
CC163  -  [C_0805]  171.12 117.13 90 bottom
CC164  -  [C_0805]  177.22 117.13 90 bottom
CC165  -  [C_0805]  173.16 117.13 90 bottom
CC166  -  [C_0805]  179 117.13 90 bottom
CC167  -  [C_D2]  178.73 78.93 0 top
CC168  -  [C_0805]  182.55 117.13 90 bottom
CC169  -  [C_0805]  184.33 117.13 90 bottom
CC170  -  [C_0805]  186.11 117.13 90 bottom
CC171  -  [C_0805]  187.89 117.13 90 bottom
CC172  -  [C_D2]  179.27 89.35 0 top
CD1  -  [C_0402]  196.96 70.76 0 top
CD2  -  [C_0402]  161.9 80.38 90 top
CD3  -  [C_0402]  161.9 77.2 90 top
CD4  -  [C_0402]  156.44 80.51 90 top
CD5  -  [C_0402]  156.44 77.46 90 top
CD6  -  [C_0402]  196.96 71.65 0 top
CD7  -  [C_0603]  150.72 77.22 90 top
CD8  -  [C_0603]  153.52 77.22 90 top
CD9  -  [C_0603]  159.1 77.22 90 top
CD10  -  [C_0603]  164.57 77.22 90 top
CD11  -  [C_0603]  150.34 80.65 90 top
CD12  -  [C_0603]  153.52 80.65 90 top
CD13  -  [C_0603]  159.1 80.52 90 top
CD14  -  [C_SX]  153.21 87.19 180 top
CD15  -  [C_0402]  147.42 77.2 90 top
CD16  -  [C_0402]  146.53 77.2 90 top
CD17  -  [C_0402]  126.21 75.17 90 top
CD18  -  [C_0402]  125.32 75.17 90 top
CD19  -  [C_0402]  119.3 66.49 180 top
CD20  -  [C_0402]  119.3 65.47 180 top
CD21  -  [C_0402]  128.37 75.17 90 top
CD22  -  [C_0402]  127.48 75.17 90 top
CD23  -  [C_0402]  195.86 63.82 0 bottom
CD24  -  [C_0402]  195.86 64.71 0 bottom
CD25  -  [C_0402]  156.44 80.51 90 bottom
CD26  -  [C_0402]  156.44 77.46 90 bottom
CD27  -  [C_0402]  161.9 80.38 90 bottom
CD28  -  [C_0402]  161.9 77.2 90 bottom
CD29  -  [C_0603]  159.1 80.52 90 bottom
CD30  -  [C_0603]  153.52 80.65 90 bottom
CD31  -  [C_0603]  150.34 80.65 90 bottom
CD32  -  [C_0603]  150.72 77.22 90 bottom
CD33  -  [C_0603]  153.52 77.22 90 bottom
CD34  -  [C_0603]  159.1 77.22 90 bottom
CD35  -  [C_0603]  164.57 77.22 90 bottom
CD36  -  [C_SX]  153.21 92.01 180 top
CD37  -  [C_0402]  119.3 71.06 180 bottom
CD38  -  [C_0402]  119.3 70.04 180 bottom
CD39  -  [C_0402]  119.3 66.49 180 bottom
CD40  -  [C_0402]  119.3 65.47 180 bottom
CD41  -  [C_0402]  147.42 77.2 90 bottom
CD42  -  [C_0402]  148.31 77.2 90 bottom
CD43  -  [C_0402]  119.3 63.44 180 bottom
CD44  -  [C_0402]  119.3 64.33 180 bottom
CD45  -  [C_0402]  196.85 63.37 0 top
CD46  -  [C_0402]  156.95 45.86 270 top
CD47  -  [C_0402]  160.63 45.86 270 top
CD48  -  [C_0402]  155.17 45.86 270 top
CD49  -  [C_0402]  196.85 62.48 0 top
CD50  -  [C_0402]  161.52 45.86 270 top
CD51  -  [C_0603]  162.79 45.85 270 top
CD52  -  [C_0603]  158.09 45.85 270 top
CD53  -  [C_0603]  152.25 45.85 270 top
CD54  -  [C_0603]  164.06 45.85 270 top
CD55  -  [C_0603]  159.49 45.85 270 top
CD56  -  [C_0603]  153.9 45.85 270 top
CD57  -  [C_0603]  150.72 45.85 270 top
CD58  -  [C_SX]  153.21 96.84 180 top
CD59  -  [C_0402]  119.26 61.84 180 top
CD60  -  [C_0402]  119.26 62.73 180 top
CD61  -  [C_0402]  129.07 46.11 270 top
CD62  -  [C_0402]  128.18 46.11 270 top
CD63  -  [C_0402]  145.52 45.86 270 top
CD64  -  [C_0402]  146.53 45.86 270 top
CD65  -  [C_0402]  119.3 62.55 180 bottom
CD66  -  [C_0402]  119.3 61.66 180 bottom
CD67  -  [C_0402]  186.92 46.37 270 bottom
CD68  -  [C_0402]  187.81 46.37 270 bottom
CD69  -  [C_0402]  156.06 45.86 270 bottom
CD70  -  [C_0402]  161.52 45.86 270 bottom
CD71  -  [C_0402]  154.91 45.86 270 bottom
CD72  -  [C_0402]  160.37 45.86 270 bottom
CD73  -  [C_0603]  150.21 45.85 270 bottom
